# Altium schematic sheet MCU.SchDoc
size A3
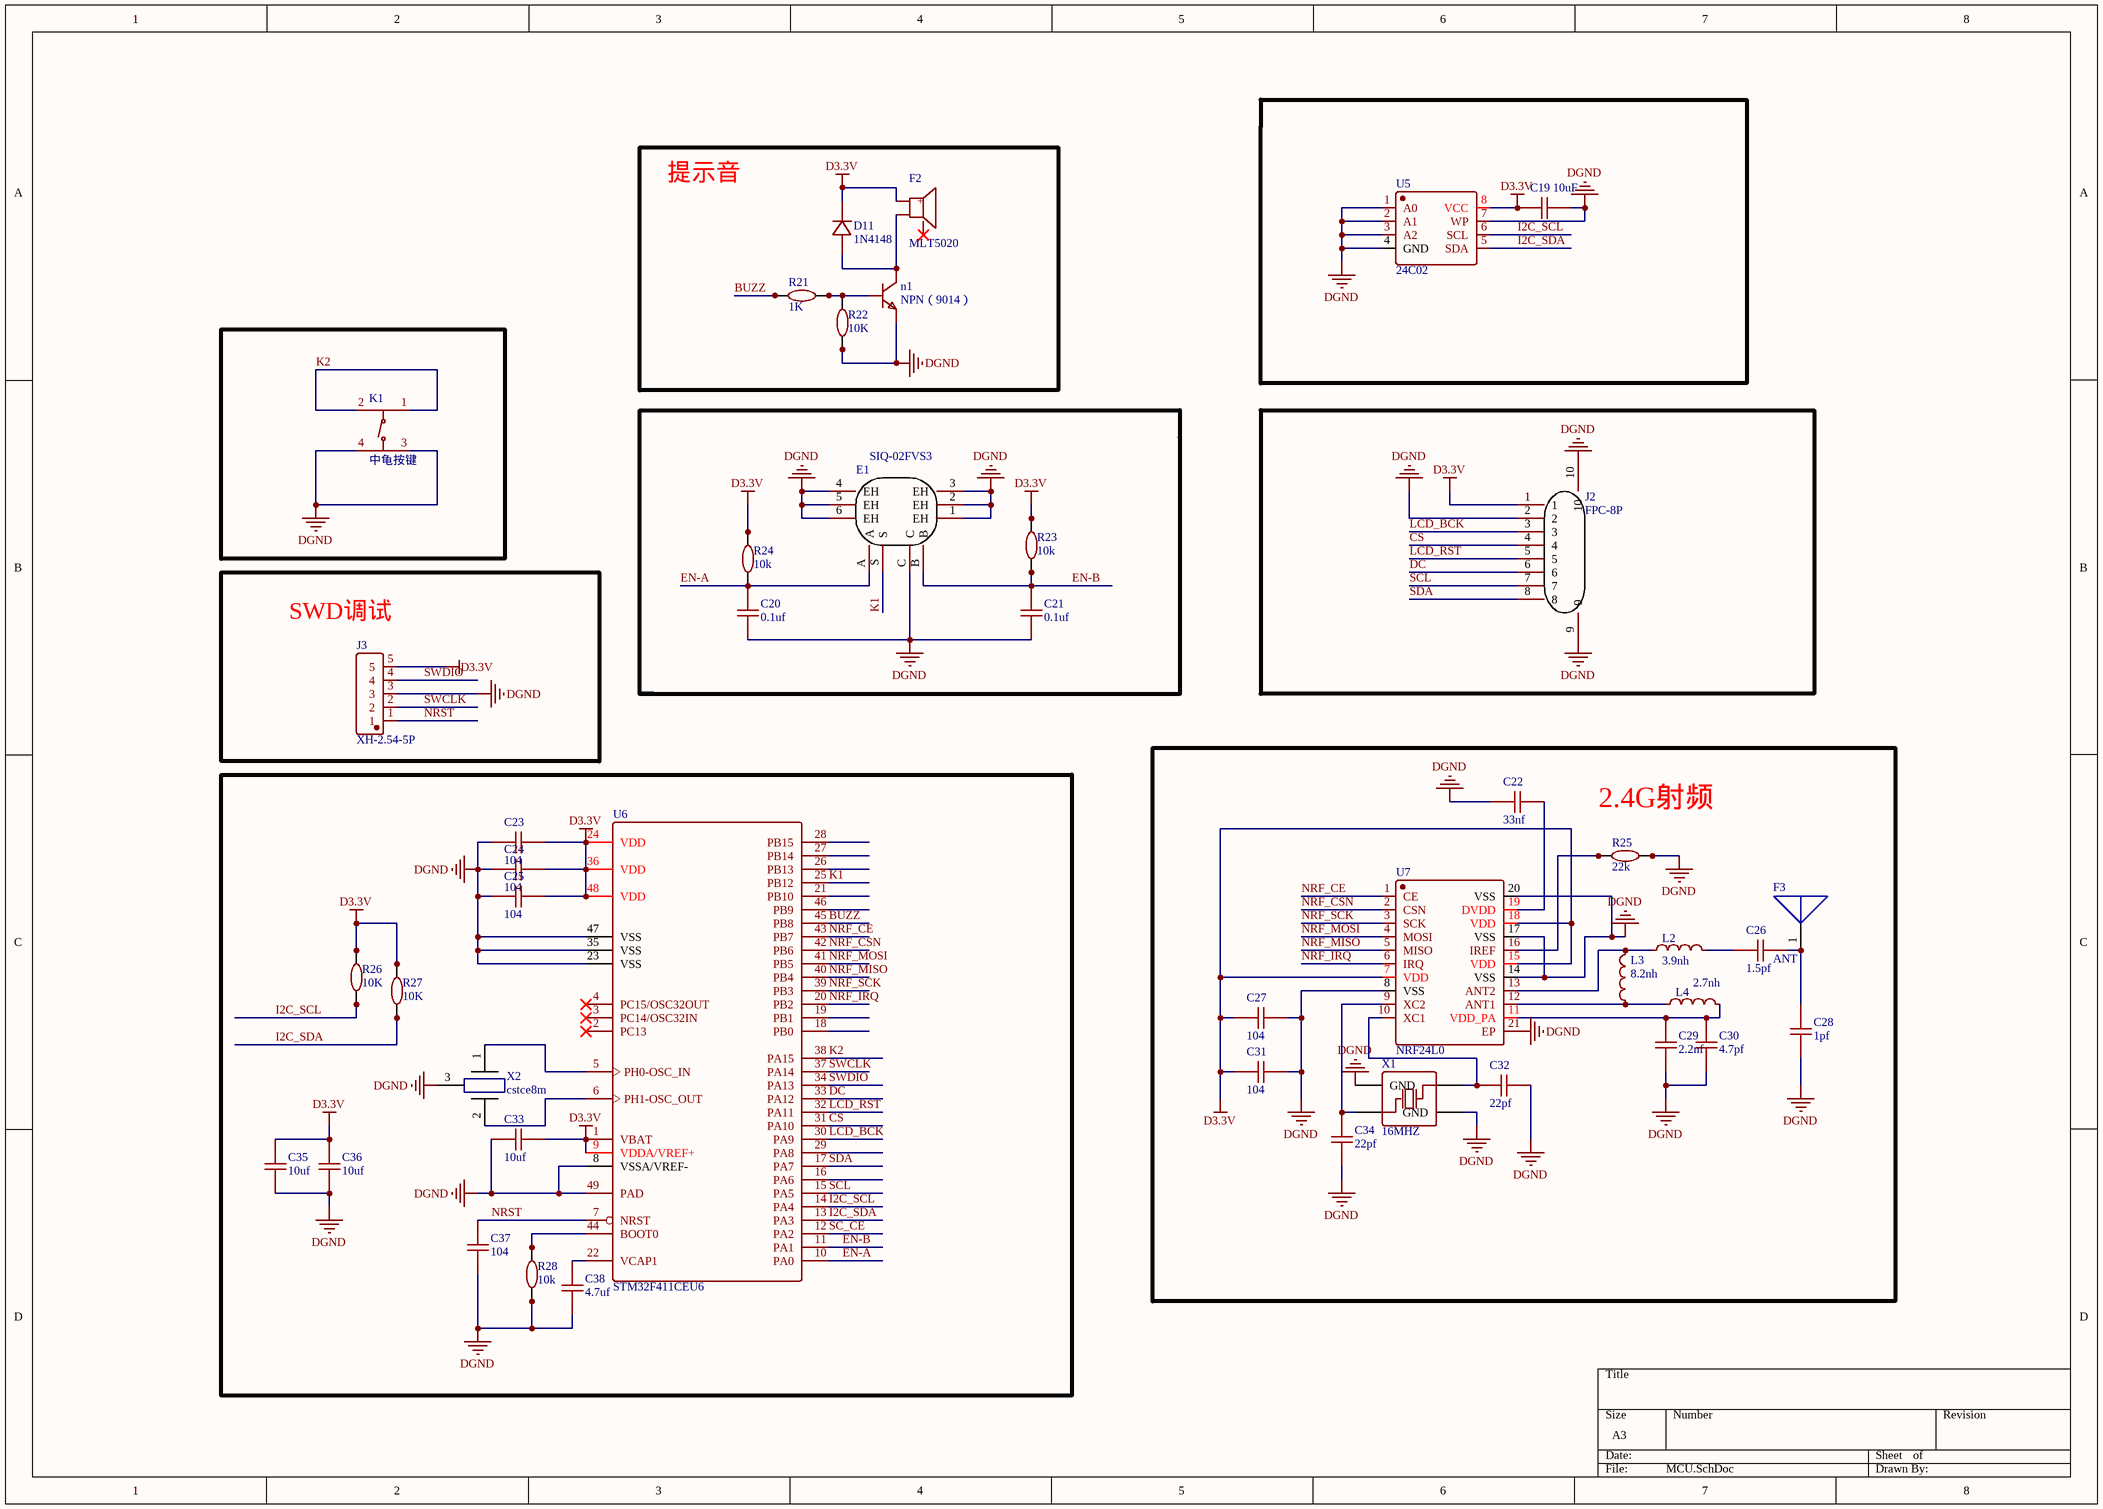
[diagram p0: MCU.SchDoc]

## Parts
C19  10uF  [C0402]
C20  0.1uf  [C0402]
C21  0.1uf  [C0402]
C22  33nf  [C0402]
C23  104  [C0402 - duplicate]
C24  104  [C0402 - duplicate]
C25  104  [C0402 - duplicate]
C26  1.5pf  [C0402]
C27  104  [C0402]
C28  1pf  [C0402]
C29  2.2nf  [C0402]
C30  4.7pf  [C0402]
C31  104  [C0402]
C32  22pf  [C0402]
C33  10uf  [C0402 - duplicate]
C34  22pf  [C0402]
C35  10uf  [C0402 - duplicate]
C36  10uf  [C0402 - duplicate]
C37  104  [C0402 - duplicate]
C38  4.7uf  [C0402 - duplicate]
D11  1N4148  [SOD-123]
E1  SIQ-02FVS3  [SIQ-02FVS3]
F2  MLT5020  [MLT5020]
F3  ANT  [AN2051]
J2  FPC-8P  [FPC-8P]
J3  XH-2.54-5P  [XH-2.54mm]
K1  中龟按键  [TS-1186F-C-A]
L2  3.9nh  [L0402]
L3  8.2nh  [L0402]
L4  2.7nh  [L0402]
n1  NPN（9014）  [SOT-23]
R21  1K  [R0603]
R22  10K  [R0603]
R23  10k  [R0402]
R24  10k  [R0402]
R25  22k  [R0402]
R26  10K  [R0402]
R27  10K  [R0402]
R28  10k  [R0402]
U5  24C02  [SOP-8]
U6  STM32F411CEU6  [UFQFPN-48]
U7  NRF24L0  [QFN20]
X1  16MHZ  [SMD3225]
X2  cstce8m  [CSTE8M]

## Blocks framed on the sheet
提示音: D11 F2 n1 R21 R22
SWD调试: J3
2.4G射频: C22 C26-C32 C34 F3 L2-L4 R25 U7 X1

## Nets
D3.3V: C19.1 C23.2 C24.2 C25.2 C27.2 C31.2 C33.1 C35.1 C36.1 D11.1(C) F2.1(+) J2.1 J3.5 R23.2 R24.2 R26.2 R27.2 U5.8(VCC) U6.1(VBAT) U6.9(VDDA/VREF+) U6.24(VDD) U6.36(VDD) U6.48(VDD) U7.7(VDD) U7.15(VDD) U7.18(VDD)
DGND: C19.2 C20.2 C21.2 C22.1 C23.1 C24.1 C25.1 C27.1 C28.1 C29.2 C30.2 C31.1 C32.2 C33.2 C34.2 C35.2 C36.2 C37.1 C38.2 E1.1(EH) E1.2(EH) E1.3(EH) E1.4(EH) E1.5(EH) E1.6(EH) E1.C J2.2 J2.9 J2.10 J3.3 K1.3 K1.4 n1.2(E) R22.2 R25.2 R28.1 U5.1(A0) U5.2(A1) U5.3(A2) U5.4(GND) U5.7(WP) U6.8(VSSA/VREF-) U6.23(VSS) U6.35(VSS) U6.47(VSS) U6.49(PAD) U7.8(VSS) U7.14(VSS) U7.17(VSS) U7.20(VSS) U7.21(EP) X1.2(GND) X1.4(GND) X2.3
BUZZ: R21.2 U6.45(PB8)
CS: J2.4 U6.31(PA10)
DC: J2.6 U6.33(PA12)
EN-A: C20.1 E1.A R24.1 U6.10(PA0)
EN-B: C21.1 E1.B R23.1 U6.11(PA1)
I2C_SCL: R26.1 U5.6(SCL) U6.14(PA4)
I2C_SDA: R27.1 U5.5(SDA) U6.13(PA3)
K1: E1.S U6.25(PB12)
K2: K1.1 K1.2 U6.38(PA15)
LCD_BCK: J2.3 U6.30(PA9)
LCD_RST: J2.5 U6.32(PA11)
NRF_CE: U6.43(PB7) U7.1(CE)
NRF_CSN: U6.42(PB6) U7.2(CSN)
NRF_IRQ: U6.20(PB2) U7.6(IRQ)
NRF_MISO: U6.40(PB4) U7.5(MISO)
NRF_MOSI: U6.41(PB5) U7.4(MOSI)
NRF_SCK: U6.39(PB3) U7.3(SCK)
NRST: C37.2 J3.1 U6.7(NRST)
SC_CE: U6.12(PA2)
SCL: J2.7 U6.15(PA5)
SDA: J2.8 U6.17(PA7)
SWCLK: J3.2 U6.37(PA14)
SWDIO: J3.4 U6.34(PA13)
NetC22_2: C22.2 U7.19(DVDD)
NetC26_1: C26.1 L2.2
NetC26_2: C26.2 C28.2 F3.1
NetC29_1: C29.1 C30.1 L4.2 U7.11(VDD_PA)
NetC32_1: C32.1 U7.10(XC1) X1.3(OSC2)
NetC34_1: C34.1 U7.9(XC2) X1.1(OSC1)
NetC38_1: C38.1 U6.22(VCAP1)
NetD11_2: D11.2(A) F2.2 n1.3(C)
NetL2_1: L2.1 L3.2 U7.13(ANT2)
NetL3_1: L3.1 L4.1 U7.12(ANT1)
Netn1_1: n1.1(B) R21.1 R22.1
NetR25_1: R25.1 U7.16(IREF)
NetR28_2: R28.2 U6.44(BOOT0)
NetU6_5: U6.5(PH0-OSC_IN) X2.1
NetU6_6: U6.6(PH1-OSC_OUT) X2.2

Not connected (* = marked no-connect by the designer): F2 3(NC)*; U6 2(PC13)* 3(PC14/OSC32IN)* 4(PC15/OSC32OUT)* 16(PA6) 18(PB0) 19(PB1) 21(PB10) 26(PB13) 27(PB14) 28(PB15) 29(PA8) 46(PB9)

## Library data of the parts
C19-C38 = 贴片电容
D11 = 1N4007
L2-L4 = 贴片电感
R21-R28 = 贴片电阻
